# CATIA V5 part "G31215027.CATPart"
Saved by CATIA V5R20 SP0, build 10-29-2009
Part number: G31215027
Revision: 4
Definition: design
Nomenclature: G31215027
Source: made
Description: NOT SPECIFIED
Bounding box of the stored display mesh (mm): x -6 to 27, y -12.31 to 12.31, z -12.5 to 12.5
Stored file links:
  C:\Users\Raffaele\Desktop\3D X SITO CF\BOLEX\23-BUSH REF 312\G31215027.CATPart

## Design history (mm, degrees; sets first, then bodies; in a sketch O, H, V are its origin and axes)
Body1 "MANIFOLD_SOLID_BREP #7667" (main body)
  Solid1: solid without history
Body2 "MANIFOLD_SOLID_BREP #7810"
  Solid2: solid without history
Body3 "MANIFOLD_SOLID_BREP #7953"
  Solid3: solid without history
Body4 "MANIFOLD_SOLID_BREP #8096"
  Solid4: solid without history
Body5 "MANIFOLD_SOLID_BREP #8239"
  Solid5: solid without history
Body6 "MANIFOLD_SOLID_BREP #8384"
  Solid6: solid without history
Body7 "MANIFOLD_SOLID_BREP #8529"
  Solid7: solid without history
Body8 "MANIFOLD_SOLID_BREP #8674"
  Solid8: solid without history
Body9 "MANIFOLD_SOLID_BREP #8819"
  Solid9: solid without history
Body10 "MANIFOLD_SOLID_BREP #8964"
  Solid10: solid without history
Body11 "MANIFOLD_SOLID_BREP #9109"
  Solid11: solid without history
Body12 "MANIFOLD_SOLID_BREP #9254"
  Solid12: solid without history
Body13 "MANIFOLD_SOLID_BREP #9399"
  Solid13: solid without history
Body14 "MANIFOLD_SOLID_BREP #9544"
  Solid14: solid without history
Body15 "MANIFOLD_SOLID_BREP #9689"
  Solid15: solid without history
Body16 "MANIFOLD_SOLID_BREP #9834"
  Solid16: solid without history
Body17 "MANIFOLD_SOLID_BREP #9979"
  Solid17: solid without history
Body18 "MANIFOLD_SOLID_BREP #10124"
  Solid18: solid without history
Body19 "MANIFOLD_SOLID_BREP #10269"
  Solid19: solid without history
Body20 "MANIFOLD_SOLID_BREP #10413"
  Solid20: solid without history
Body21 "MANIFOLD_SOLID_BREP #10556"
  Solid21: solid without history
Body22 "MANIFOLD_SOLID_BREP #10701"
  Solid22: solid without history
Body23 "MANIFOLD_SOLID_BREP #10845"
  Solid23: solid without history
Body24 "MANIFOLD_SOLID_BREP #10988"
  Solid24: solid without history
Body25 "MANIFOLD_SOLID_BREP #11133"
  Solid25: solid without history
Body26 "MANIFOLD_SOLID_BREP #11278"
  Solid26: solid without history
Body27 "MANIFOLD_SOLID_BREP #11423"
  Solid27: solid without history
Body28 "MANIFOLD_SOLID_BREP #11568"
  Solid28: solid without history
Body29 "MANIFOLD_SOLID_BREP #11713"
  Solid29: solid without history
Body30 "MANIFOLD_SOLID_BREP #11858"
  Solid30: solid without history
Body31 "MANIFOLD_SOLID_BREP #12003"
  Solid31: solid without history
Body32 "MANIFOLD_SOLID_BREP #12146"
  Solid32: solid without history
Body33 "MANIFOLD_SOLID_BREP #12289"
  Solid33: solid without history
Body34 "MANIFOLD_SOLID_BREP #12434"
  Solid34: solid without history
Body35 "MANIFOLD_SOLID_BREP #12579"
  Solid35: solid without history
Body36 "MANIFOLD_SOLID_BREP #12723"
  Solid36: solid without history
Body37 "MANIFOLD_SOLID_BREP #12866"
  Solid37: solid without history
Body38 "MANIFOLD_SOLID_BREP #13011"
  Solid38: solid without history
Body39 "MANIFOLD_SOLID_BREP #13155"
  Solid39: solid without history
Body40 "MANIFOLD_SOLID_BREP #13298"
  Solid40: solid without history
Body41 "MANIFOLD_SOLID_BREP #13443"
  Solid41: solid without history
Body42 "MANIFOLD_SOLID_BREP #13588"
  Solid42: solid without history
Body43 "MANIFOLD_SOLID_BREP #13733"
  Solid43: solid without history
Body44 "MANIFOLD_SOLID_BREP #13878"
  Solid44: solid without history
Body45 "MANIFOLD_SOLID_BREP #14023"
  Solid45: solid without history
Body46 "MANIFOLD_SOLID_BREP #14168"
  Solid46: solid without history
Body47 "MANIFOLD_SOLID_BREP #14313"
  Solid47: solid without history
Body48 "MANIFOLD_SOLID_BREP #14458"
  Solid48: solid without history
Body49 "MANIFOLD_SOLID_BREP #14603"
  Solid49: solid without history
Body50 "MANIFOLD_SOLID_BREP #14747"
  Solid50: solid without history
Body51 "MANIFOLD_SOLID_BREP #14890"
  Solid51: solid without history
Body52 "MANIFOLD_SOLID_BREP #15035"
  Solid52: solid without history
Body53 "MANIFOLD_SOLID_BREP #15179"
  Solid53: solid without history
Body54 "MANIFOLD_SOLID_BREP #15322"
  Solid54: solid without history
Body55 "MANIFOLD_SOLID_BREP #15467"
  Solid55: solid without history
Body56 "MANIFOLD_SOLID_BREP #15610"
  Solid56: solid without history
Body57 "MANIFOLD_SOLID_BREP #15753"
  Solid57: solid without history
